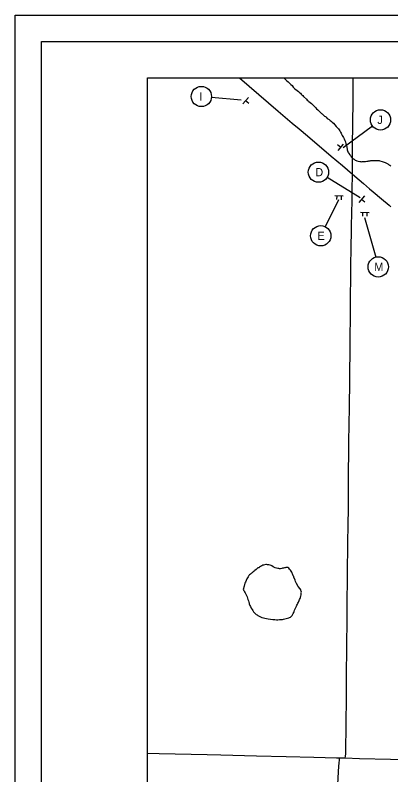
# Model space of a CAD drawing. Extents: x 1651.5 to 1685.5, y 1084.6 to 1106.6.
# Drawn here: x 1651.46 to 1658.64, y 1092.09 to 1106.6 of the extents above; entities that cross this region are included whole.
import ezdxf

# ---------------------------------------------------------------- set-up
doc = ezdxf.new("R2010")
doc.units = 0
for name, color, linetype in [('GM_X_County_Road', 7, 'Continuous'), ('GM_X_Minor_Lake', 7, 'Continuous'), ('GM_X_Minor_River', 7, 'Continuous'), ('GM_X_State_Route', 7, 'Continuous'), ('GM_X_Township_Road', 7, 'Continuous'), ('SC_Scratch1', 7, 'Continuous'), ('SH_Border', 7, 'Continuous'), ('SH_Data', 7, 'Continuous'), ('SH_Text', 7, 'Continuous'), ('SN_P_Signs', 7, 'Continuous')]:
    doc.layers.add(name, color=color, linetype=linetype)

msp = doc.modelspace()

# ---------------------------------------------------------------- linework, layer by layer
at = {"layer": 'GM_X_County_Road'}
for points in [[(1657.906, 1103.565), (1657.906, 1103.852), (1657.908, 1104.093), (1657.917, 1104.967), (1657.917, 1105.186), (1657.922, 1105.401)], [(1657.766, 1092.408), (1657.771, 1092.433), (1657.775, 1092.463), (1657.777, 1092.477), (1657.779, 1092.513), (1657.782, 1092.615), (1657.784, 1092.96), (1657.791, 1093.661), (1657.794, 1094.033), (1657.794, 1094.12), (1657.799, 1094.382), (1657.8, 1094.601), (1657.804, 1094.995), (1657.807, 1095.301), (1657.821, 1096.527), (1657.824, 1096.855), (1657.828, 1097.182), (1657.833, 1097.663), (1657.84, 1098.451), (1657.847, 1099.108), (1657.853, 1099.611), (1657.865, 1100.333), (1657.871, 1100.946), (1657.877, 1101.865), (1657.88, 1102.106), (1657.886, 1102.544), (1657.895, 1102.85), (1657.898, 1103.025), (1657.901, 1103.332), (1657.904, 1103.484), (1657.906, 1103.565)], [(1657.466, 1088.971), (1657.494, 1089.549), (1657.562, 1090.772), (1657.591, 1091.253), (1657.612, 1091.668), (1657.646, 1092.258), (1657.65, 1092.305), (1657.657, 1092.377), (1657.66, 1092.411)], [(1657.66, 1092.411), (1657.766, 1092.408)]]:
    msp.add_lwpolyline(points, dxfattribs=at)
at = {"layer": 'GM_X_Minor_Lake'}
for points in [[(1656.867, 1095.686), (1656.836, 1095.744), (1656.826, 1095.766), (1656.82, 1095.779), (1656.813, 1095.803), (1656.789, 1095.86), (1656.784, 1095.873), (1656.776, 1095.89), (1656.768, 1095.908), (1656.761, 1095.925), (1656.753, 1095.941), (1656.745, 1095.957), (1656.734, 1095.976), (1656.724, 1095.997), (1656.705, 1096.016), (1656.692, 1096.033), (1656.671, 1096.046), (1656.652, 1096.049), (1656.636, 1096.047), (1656.622, 1096.044), (1656.606, 1096.042), (1656.587, 1096.037), (1656.571, 1096.034), (1656.555, 1096.029), (1656.533, 1096.024), (1656.512, 1096.024), (1656.499, 1096.025), (1656.48, 1096.027), (1656.458, 1096.033), (1656.432, 1096.041), (1656.405, 1096.055), (1656.392, 1096.063), (1656.368, 1096.077), (1656.352, 1096.083), (1656.333, 1096.091), (1656.306, 1096.097), (1656.282, 1096.1), (1656.263, 1096.103), (1656.25, 1096.103), (1656.204, 1096.095), (1656.191, 1096.09), (1656.174, 1096.08), (1656.15, 1096.064), (1656.128, 1096.051), (1656.115, 1096.043), (1656.101, 1096.038), (1656.085, 1096.027), (1656.069, 1096.011), (1656.044, 1095.99), (1656.031, 1095.98), (1656.009, 1095.964), (1655.99, 1095.948), (1655.977, 1095.938), (1655.958, 1095.922), (1655.939, 1095.906), (1655.928, 1095.893), (1655.911, 1095.871), (1655.898, 1095.853), (1655.889, 1095.832), (1655.881, 1095.816), (1655.875, 1095.8), (1655.864, 1095.77), (1655.853, 1095.749), (1655.845, 1095.722), (1655.837, 1095.691)], [(1655.837, 1095.691), (1655.819, 1095.628), (1655.83, 1095.61), (1655.841, 1095.585), (1655.854, 1095.564), (1655.894, 1095.489), (1655.902, 1095.462), (1655.907, 1095.435), (1655.918, 1095.409), (1655.926, 1095.385), (1655.931, 1095.371), (1655.936, 1095.352), (1655.944, 1095.323), (1655.958, 1095.301), (1655.974, 1095.272), (1655.99, 1095.245), (1656.003, 1095.224), (1656.016, 1095.202), (1656.03, 1095.186), (1656.051, 1095.165), (1656.064, 1095.151), (1656.083, 1095.141), (1656.099, 1095.13), (1656.123, 1095.116), (1656.147, 1095.103), (1656.177, 1095.092), (1656.206, 1095.084), (1656.233, 1095.079), (1656.262, 1095.073), (1656.297, 1095.068), (1656.34, 1095.059), (1656.388, 1095.054), (1656.425, 1095.051), (1656.457, 1095.048), (1656.481, 1095.048), (1656.514, 1095.051), (1656.538, 1095.051), (1656.567, 1095.053), (1656.591, 1095.061), (1656.615, 1095.067), (1656.642, 1095.072), (1656.666, 1095.08), (1656.688, 1095.085), (1656.704, 1095.09), (1656.72, 1095.098), (1656.733, 1095.112), (1656.752, 1095.128), (1656.763, 1095.144), (1656.773, 1095.168), (1656.784, 1095.186), (1656.792, 1095.205), (1656.8, 1095.232), (1656.83, 1095.293), (1656.835, 1095.307), (1656.846, 1095.325), (1656.854, 1095.349), (1656.865, 1095.365), (1656.873, 1095.384), (1656.881, 1095.4), (1656.889, 1095.419), (1656.897, 1095.438), (1656.905, 1095.456), (1656.911, 1095.472), (1656.916, 1095.486), (1656.919, 1095.502), (1656.924, 1095.523), (1656.927, 1095.545), (1656.927, 1095.566), (1656.93, 1095.579), (1656.927, 1095.593), (1656.922, 1095.609), (1656.919, 1095.622), (1656.906, 1095.641), (1656.867, 1095.686)]]:
    msp.add_lwpolyline(points, dxfattribs=at)
at = {"layer": 'GM_X_Minor_River'}
for points in [[(1656.596, 1105.401), (1656.624, 1105.371), (1656.654, 1105.347), (1656.677, 1105.328), (1656.693, 1105.314), (1656.709, 1105.295), (1656.731, 1105.276), (1656.752, 1105.255), (1656.776, 1105.225)], [(1656.776, 1105.225), (1656.807, 1105.195), (1656.853, 1105.16), (1656.874, 1105.14), (1656.892, 1105.124), (1656.911, 1105.108), (1656.924, 1105.094), (1656.94, 1105.081), (1656.956, 1105.064), (1656.972, 1105.048), (1657.028, 1104.999), (1657.041, 1104.98), (1657.06, 1104.967), (1657.076, 1104.95), (1657.099, 1104.931), (1657.123, 1104.912), (1657.142, 1104.893), (1657.161, 1104.877), (1657.179, 1104.858), (1657.198, 1104.834), (1657.221, 1104.809), (1657.243, 1104.79), (1657.261, 1104.774), (1657.283, 1104.755), (1657.301, 1104.738), (1657.314, 1104.725), (1657.328, 1104.717), (1657.341, 1104.706), (1657.354, 1104.69), (1657.373, 1104.671), (1657.389, 1104.662), (1657.402, 1104.649), (1657.423, 1104.624), (1657.447, 1104.613), (1657.461, 1104.605), (1657.482, 1104.589), (1657.501, 1104.575), (1657.519, 1104.559), (1657.543, 1104.537), (1657.567, 1104.507), (1657.596, 1104.475), (1657.622, 1104.45), (1657.638, 1104.431), (1657.652, 1104.41), (1657.665, 1104.391), (1657.678, 1104.367), (1657.691, 1104.348), (1657.699, 1104.329), (1657.712, 1104.304), (1657.725, 1104.283), (1657.733, 1104.264), (1657.746, 1104.237), (1657.759, 1104.205), (1657.772, 1104.178), (1657.782, 1104.143), (1657.793, 1104.113), (1657.798, 1104.086), (1657.808, 1104.03), (1657.813, 1104.008), (1657.818, 1103.987), (1657.829, 1103.971), (1657.839, 1103.955), (1657.855, 1103.93), (1657.866, 1103.917), (1657.879, 1103.895), (1657.905, 1103.871), (1657.924, 1103.857), (1657.937, 1103.849), (1657.958, 1103.832), (1657.975, 1103.827), (1657.993, 1103.819), (1658.017, 1103.81), (1658.044, 1103.805), (1658.065, 1103.802), (1658.084, 1103.801), (1658.098, 1103.804), (1658.114, 1103.804), (1658.13, 1103.806), (1658.154, 1103.808), (1658.181, 1103.813), (1658.205, 1103.813), (1658.219, 1103.816), (1658.243, 1103.818), (1658.256, 1103.821), (1658.278, 1103.823), (1658.299, 1103.823), (1658.316, 1103.822), (1658.337, 1103.825), (1658.359, 1103.825), (1658.375, 1103.824), (1658.393, 1103.821), (1658.415, 1103.821), (1658.431, 1103.818), (1658.471, 1103.807), (1658.492, 1103.799), (1658.511, 1103.793), (1658.53, 1103.785), (1658.546, 1103.779), (1658.559, 1103.774), (1658.581, 1103.76), (1658.597, 1103.749)], [(1658.597, 1103.749), (1658.618, 1103.735), (1658.639, 1103.719)]]:
    msp.add_lwpolyline(points, dxfattribs=at)
at = {"layer": 'GM_X_State_Route'}
for points in [[(1655.748, 1105.401), (1656.489, 1104.768), (1656.755, 1104.54), (1656.887, 1104.427), (1657.046, 1104.298), (1657.497, 1103.905), (1657.716, 1103.727), (1657.906, 1103.565), (1657.954, 1103.523)], [(1657.954, 1103.523), (1658.117, 1103.385), (1658.234, 1103.285), (1658.304, 1103.225), (1658.459, 1103.092), (1658.606, 1102.971), (1658.642, 1102.938)]]:
    msp.add_lwpolyline(points, dxfattribs=at)
at = {"layer": 'GM_X_Township_Road'}
for points in [[(1653.988, 1092.498), (1654.213, 1092.493), (1655.132, 1092.472), (1655.394, 1092.465), (1656.072, 1092.449), (1656.641, 1092.435), (1657.166, 1092.422), (1657.603, 1092.413), (1657.66, 1092.411)], [(1657.766, 1092.408), (1658.041, 1092.399), (1658.631, 1092.386), (1660.162, 1092.348), (1660.643, 1092.336), (1661.212, 1092.32), (1661.304, 1092.318)]]:
    msp.add_lwpolyline(points, dxfattribs=at)
at = {"layer": 'SC_Scratch1'}
msp.add_lwpolyline([(1651.463, 1106.601), (1685.463, 1106.601), (1685.463, 1084.601), (1651.463, 1084.601)], close=True, dxfattribs=at)
at = {"layer": 'SH_Border'}
msp.add_lwpolyline([(1651.963, 1106.101), (1684.963, 1106.101), (1684.963, 1085.101), (1651.963, 1085.101)], close=True, dxfattribs=at)
at = {"layer": 'SH_Data'}
msp.add_lwpolyline([(1653.988, 1105.401), (1668.688, 1105.401), (1668.688, 1085.801), (1653.988, 1085.801)], close=True, dxfattribs=at)
at = {"layer": 'SH_Text'}
for p, q in [((1655.783, 1104.978), (1655.213, 1105.028)), ((1657.728, 1104.072), (1658.286, 1104.486)), ((1658.054, 1103.11), (1657.422, 1103.499)), ((1657.641, 1103.072), (1657.388, 1102.558)), ((1658.134, 1102.737), (1658.352, 1101.979))]:
    msp.add_line(p, q, dxfattribs=at)
msp.add_lwpolyline([(1657.906, 1103.565), (1658.117, 1103.385), (1658.234, 1103.285), (1658.304, 1103.225), (1658.459, 1103.092), (1658.606, 1102.971), (1658.642, 1102.938)], dxfattribs=at)
for centre in [(1655.02, 1105.047), (1658.442, 1104.6), (1657.257, 1103.601), (1657.3, 1102.385), (1658.399, 1101.791)]:
    msp.add_circle(centre, 0.194, dxfattribs=at)
at = {"layer": 'SN_P_Signs'}
for p, q in [((1655.918, 1105.031), (1655.814, 1104.91)), ((1655.866, 1104.97), (1655.927, 1104.918)), ((1657.684, 1104.075), (1657.623, 1104.126)), ((1657.633, 1104.014), (1657.736, 1104.136)), ((1657.569, 1103.153), (1657.729, 1103.148)), ((1657.606, 1103.152), (1657.604, 1103.077)), ((1657.69, 1103.149), (1657.688, 1103.074)), ((1658.134, 1103.146), (1658.03, 1103.024)), ((1658.082, 1103.085), (1658.143, 1103.033)), ((1658.063, 1102.838), (1658.223, 1102.833)), ((1658.1, 1102.837), (1658.098, 1102.761)), ((1658.184, 1102.834), (1658.182, 1102.759))]:
    msp.add_line(p, q, dxfattribs=at)

# ---------------------------------------------------------------- texts
at = {"layer": 'SH_Text'}
for s, p in [('I', (1654.979, 1104.969)), ('J', (1658.381, 1104.522)), ('D', (1657.196, 1103.523)), ('E', (1657.237, 1102.307)), ('M', (1658.323, 1101.713))]:
    msp.add_text(s, height=0.156, dxfattribs=at).set_placement(p)

doc.saveas('drawing.dxf')
